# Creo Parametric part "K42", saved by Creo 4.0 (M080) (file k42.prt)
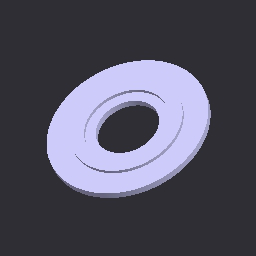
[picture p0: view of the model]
Units: Inch lbm Second (Pro/E Default); INCH, POUND, SECS

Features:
  1. datum plane "DTM3"
  2. datum plane "DTM4"
  3. datum plane "DTM5"
  4. protrusion

Layers: BASE_DAT, BLANK

Surfaces: 8 cylinder, 4 plane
